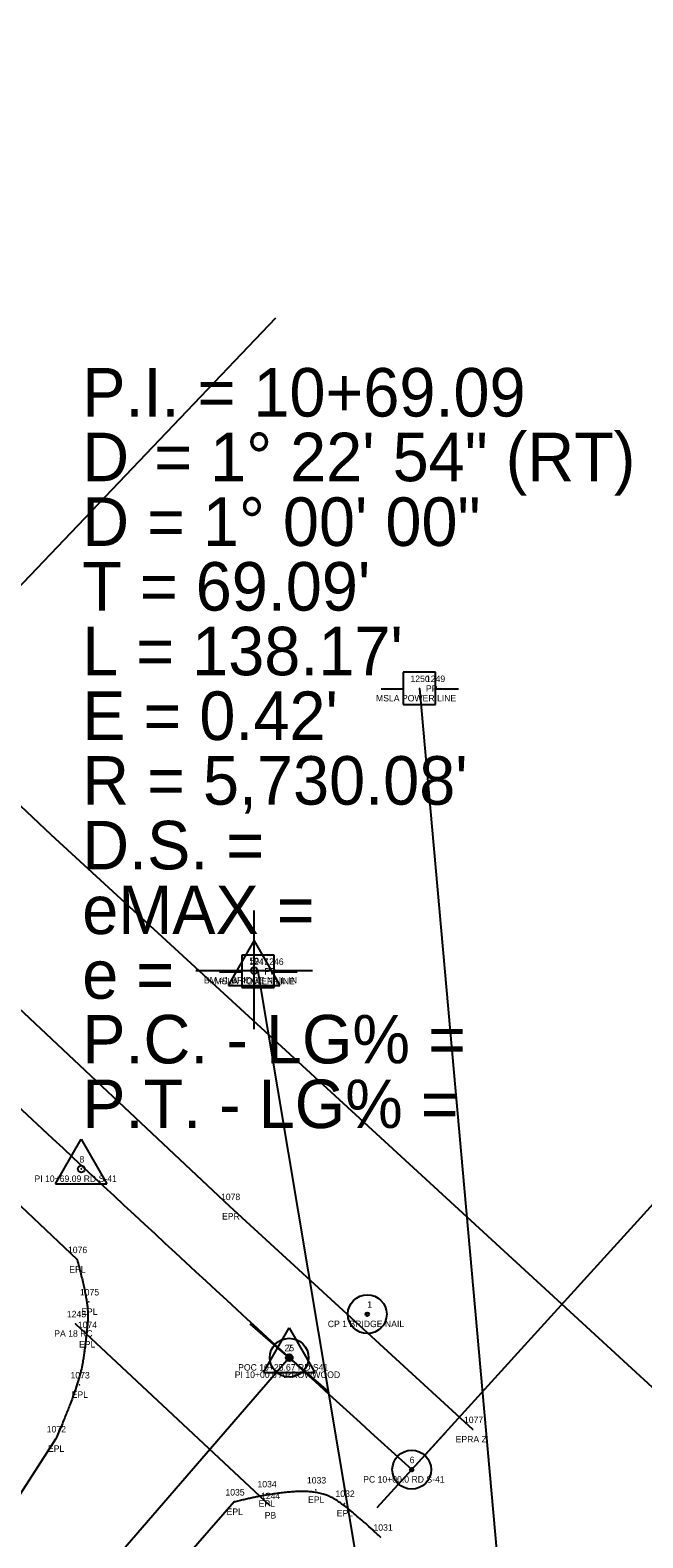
# Model space of a CAD drawing. Extents: x 1812113 to 1819860, y 1177290 to 1181185.
# Drawn here: x 1814007.9 to 1814102.7, y 1178410.7 to 1178643.7 of the extents above; entities that cross this region are included whole.
import ezdxf

# ---------------------------------------------------------------- set-up
doc = ezdxf.new("R2010")
doc.units = 0
for name, color, linetype in [('RD_EX_DR_Pipe', 7, 'Continuous'), ('RD_EX_DR_Pipe_txCode', 7, 'Continuous'), ('RD_EX_DV_Prop', 7, 'Continuous'), ('RD_EX_Misc', 7, 'Continuous'), ('RD_EX_Misc_txCode', 7, 'Continuous'), ('RD_EX_Road', 7, 'Continuous'), ('RD_EX_Road_txCode', 7, 'Continuous'), ('RD_EX_UT', 7, 'Continuous'), ('RD_EX_UT_txCode', 7, 'Continuous'), ('RD_HC_CL', 7, 'Continuous'), ('RD_HC_Data', 7, 'Continuous'), ('RD_HC_Data_Tic', 7, 'Continuous'), ('RD_HC_TX_StaOther', 7, 'Continuous'), ('RD_HC_txCode', 7, 'Continuous'), ('RD_SMD_Locator', 7, 'Continuous')]:
    doc.layers.add(name, color=color, linetype=linetype)

msp = doc.modelspace()

# ---------------------------------------------------------------- linework, layer by layer
at = {"layer": 'RD_EX_DR_Pipe'}
msp.add_line((1814014.96, 1178443.75), (1814045.01, 1178415.64), dxfattribs=at)
at = {"layer": 'RD_EX_DV_Prop'}
for p, q in [((1814011.17, 1178519.35), (1813854.67, 1178667.32)), ((1814146.51, 1178395.03), (1814011.17, 1178519.35))]:
    msp.add_line(p, q, dxfattribs=at)
at = {"layer": 'RD_EX_Misc'}
for p, q in [((1814068.17, 1178541.96), (1814086.12, 1178341.27)), ((1814043.18, 1178498.23), (1814070.2, 1178336.93))]:
    msp.add_line(p, q, dxfattribs=at)
at = {"layer": 'RD_EX_Road'}
for p, q in [((1814015.19, 1178453.67), (1813986.47, 1178480.85)), ((1814001.91, 1178410.56), (1814011.9, 1178425.95)), ((1814039.53, 1178416.2), (1814027.18, 1178402.17))]:
    msp.add_line(p, q, dxfattribs=at)
msp.add_lwpolyline([(1814076.45, 1178427.4), (1814038.86, 1178461.87), (1814001.83, 1178496.62), (1813965.15, 1178531.54), (1813928.08, 1178567.1), (1813892.01, 1178601.23), (1813854.54, 1178636.51), (1813817.44, 1178670.03), (1813779.87, 1178701.64)], dxfattribs=at)
for points in [[(1814015.19, 1178453.67), (1814017.03, 1178447.13), (1814016.71, 1178442.08), (1814015.58, 1178434.3), (1814011.9, 1178425.95)], [(1814062.16, 1178410.76), (1814056.57, 1178415.98), (1814052.15, 1178418.06), (1814044.5, 1178417.46), (1814039.53, 1178416.2)]]:
    msp.add_open_spline(points, degree=2, dxfattribs=at)
at = {"layer": 'RD_EX_UT'}
for p, q in [((1814070.66, 1178544.47), (1814065.66, 1178544.47)), ((1814065.66, 1178544.47), (1814065.66, 1178539.47)), ((1814070.66, 1178539.47), (1814070.66, 1178544.47)), ((1814062.23, 1178541.91), (1814065.7, 1178541.91)), ((1814070.59, 1178541.91), (1814074.23, 1178541.91)), ((1814065.66, 1178539.47), (1814070.66, 1178539.47)), ((1814045.67, 1178500.74), (1814040.67, 1178500.74)), ((1814040.67, 1178500.74), (1814040.67, 1178495.74)), ((1814045.67, 1178495.74), (1814045.67, 1178500.74)), ((1814037.24, 1178498.17), (1814040.71, 1178498.17)), ((1814045.6, 1178498.17), (1814049.24, 1178498.17)), ((1814040.67, 1178495.74), (1814045.67, 1178495.74))]:
    msp.add_line(p, q, dxfattribs=at)
at = {"layer": 'RD_HC_CL'}
msp.add_line((1814048.02, 1178438.51), (1813851.74, 1178211.63), dxfattribs=at)
msp.add_arc((1817921.84, 1182660.75), 5730.08, 226.33932, 227.720866, dxfattribs=at)
at = {"layer": 'RD_HC_Data'}
for p, q in [((1813965.88, 1178515.37), (1814045.93, 1178599.26)), ((1814042.6, 1178489.32), (1814042.6, 1178507.65)), ((1814066.97, 1178421.2), (1814145.47, 1178507.54)), ((1814038.63, 1178496.06), (1814042.6, 1178502.94)), ((1814042.6, 1178502.94), (1814046.57, 1178496.06)), ((1814033.56, 1178498.36), (1814051.64, 1178498.36)), ((1814038.63, 1178496.06), (1814046.57, 1178496.06)), ((1814011.88, 1178465.39), (1814015.86, 1178472.27)), ((1814015.86, 1178472.27), (1814019.83, 1178465.39)), ((1814011.88, 1178465.39), (1814019.83, 1178465.39)), ((1814044.05, 1178436.22), (1814048.02, 1178443.1)), ((1814048.02, 1178443.1), (1814051.99, 1178436.22)), ((1814044.05, 1178436.22), (1814051.99, 1178436.22))]:
    msp.add_line(p, q, dxfattribs=at)
for centre, radius in [((1814042.6, 1178498.36), 0.529), ((1814015.86, 1178467.68), 0.529), ((1814060.1, 1178445.23), 3), ((1814060.1, 1178445.23), 0.282), ((1814048.02, 1178438.51), 3), ((1814048.02, 1178438.51), 0.529), ((1814048.02, 1178438.51), 0.282), ((1814066.97, 1178421.2), 3), ((1814066.97, 1178421.2), 0.282)]:
    msp.add_circle(centre, radius, dxfattribs=at)
at = {"layer": 'RD_HC_Data_Tic'}
for p, q in [((1814048.02, 1178438.51), (1814041.97, 1178443.74)), ((1814048.02, 1178438.51), (1814054.07, 1178433.28)), ((1814066.97, 1178421.2), (1814072.35, 1178427.12)), ((1814066.97, 1178421.2), (1814061.59, 1178415.28))]:
    msp.add_line(p, q, dxfattribs=at)
at = {"layer": 'RD_SMD_Locator'}
for centre in [(1814068.17, 1178541.96), (1814042.6, 1178498.36), (1814043.18, 1178498.23), (1814015.86, 1178467.68), (1814038.86, 1178461.87), (1814015.19, 1178453.67), (1814017.03, 1178447.13), (1814014.96, 1178443.75), (1814060.1, 1178445.23), (1814016.71, 1178442.08), (1814048.02, 1178438.51), (1814048.02, 1178438.51), (1814015.58, 1178434.3), (1814076.45, 1178427.4), (1814011.9, 1178425.95), (1814066.97, 1178421.2), (1814052.15, 1178418.06), (1814039.53, 1178416.2), (1814044.5, 1178417.46), (1814045.01, 1178415.64), (1814056.57, 1178415.98), (1814062.16, 1178410.76)]:
    msp.add_circle(centre, 0.001, dxfattribs=at)

# ---------------------------------------------------------------- texts
at = {"layer": 'RD_EX_DR_Pipe_txCode'}
for s, p in [('1243', (1814013.62, 1178444.75)), ('PA 18 RC', (1814011.67, 1178441.75)), ('1244', (1814043.66, 1178416.64)), ('PB', (1814044.23, 1178413.64))]:
    msp.add_text(s, height=1, dxfattribs=at).set_placement(p)
at = {"layer": 'RD_EX_Misc_txCode'}
for s, p in [('1250', (1814066.78, 1178542.96)), ('MSLA POWER LINE', (1814061.45, 1178539.96)), ('1247', (1814041.83, 1178499.23)), ('MSLA POWER LINE', (1814036.47, 1178496.23))]:
    msp.add_text(s, height=1, dxfattribs=at).set_placement(p)
at = {"layer": 'RD_EX_Road_txCode'}
for s, p in [('1078', (1814037.47, 1178462.87)), ('EPR', (1814037.63, 1178459.87)), ('1076', (1814013.79, 1178454.67)), ('EPL', (1814013.99, 1178451.67)), ('1075', (1814015.64, 1178448.13)), ('EPL', (1814015.83, 1178445.13)), ('1074', (1814015.32, 1178443.08)), ('EPL', (1814015.5, 1178440.08)), ('1073', (1814014.19, 1178435.3)), ('EPL', (1814014.37, 1178432.3)), ('1077', (1814075.06, 1178428.4)), ('1072', (1814010.51, 1178426.95)), ('EPL', (1814010.69, 1178423.95)), ('EPRA Z', (1814073.77, 1178425.4)), ('1033', (1814050.76, 1178419.06)), ('1035', (1814038.15, 1178417.2)), ('1034', (1814043.11, 1178418.46)), ('1032', (1814055.18, 1178416.98)), ('EPL', (1814043.29, 1178415.46)), ('EPL', (1814050.94, 1178416.06)), ('EPL', (1814038.33, 1178414.2)), ('EPL', (1814055.37, 1178413.98)), ('1031', (1814061.06, 1178411.76))]:
    msp.add_text(s, height=1, dxfattribs=at).set_placement(p)
at = {"layer": 'RD_EX_UT_txCode'}
for s, p in [('1249', (1814069.17, 1178542.96)), ('PP', (1814069.17, 1178541.46)), ('1246', (1814044.18, 1178499.23)), ('PP', (1814044.18, 1178497.73))]:
    msp.add_text(s, height=1, dxfattribs=at).set_placement(p)
at = {"layer": 'RD_HC_TX_StaOther'}
for s, p in [('P.I. = 10+69.09', (1814016, 1178584)), ('D', (1814016, 1178574)), ('    = 1%%d 22\' 54" (RT)', (1814016, 1178574)), ('D = 1%%d 00\' 00"', (1814016, 1178564)), ("T = 69.09'", (1814016, 1178554)), ("L = 138.17'", (1814016, 1178544)), ("E = 0.42'", (1814016, 1178534)), ("R = 5,730.08'", (1814016, 1178524)), ('D.S. = ', (1814016, 1178514)), ('eMAX = ', (1814016, 1178504)), ('e = ', (1814016, 1178494)), ('P.C. - LG% = ', (1814016, 1178484)), ('P.T. - LG% = ', (1814016, 1178474))]:
    msp.add_text(s, height=7.5, dxfattribs=at).set_placement(p)
at = {"layer": 'RD_HC_txCode'}
for s, p in [('59', (1814041.87, 1178499.36)), ('BM #1 BRIDGE NAIL IN', (1814034.83, 1178496.36)), ('8', (1814015.57, 1178468.68)), ('PI 10+69.09 RD S-41', (1814008.61, 1178465.68)), ('1', (1814060.1, 1178446.23)), ('CP 1 BRIDGE NAIL', (1814053.99, 1178443.23)), ('25', (1814047.29, 1178439.51)), ('7', (1814047.74, 1178439.51)), ('PI 10+00.0 ARROWWOOD', (1814039.6, 1178435.38)), ('POC 10+25.67 RD S41', (1814040.12, 1178436.51)), ('6', (1814066.66, 1178422.2)), ('PC 10+00.0 RD S-41', (1814059.47, 1178419.2))]:
    msp.add_text(s, height=1, dxfattribs=at).set_placement(p)

doc.saveas('drawing.dxf')
